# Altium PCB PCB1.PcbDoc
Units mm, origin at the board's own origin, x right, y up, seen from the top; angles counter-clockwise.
Board outline 70 x 70 mm, 4 copper layers (Top Layer, Internal Plane 1, Internal Plane 2, Bottom Layer), stack 0.462 mm thick; 10 components, 13 nets, 53 pads, 0 vias.
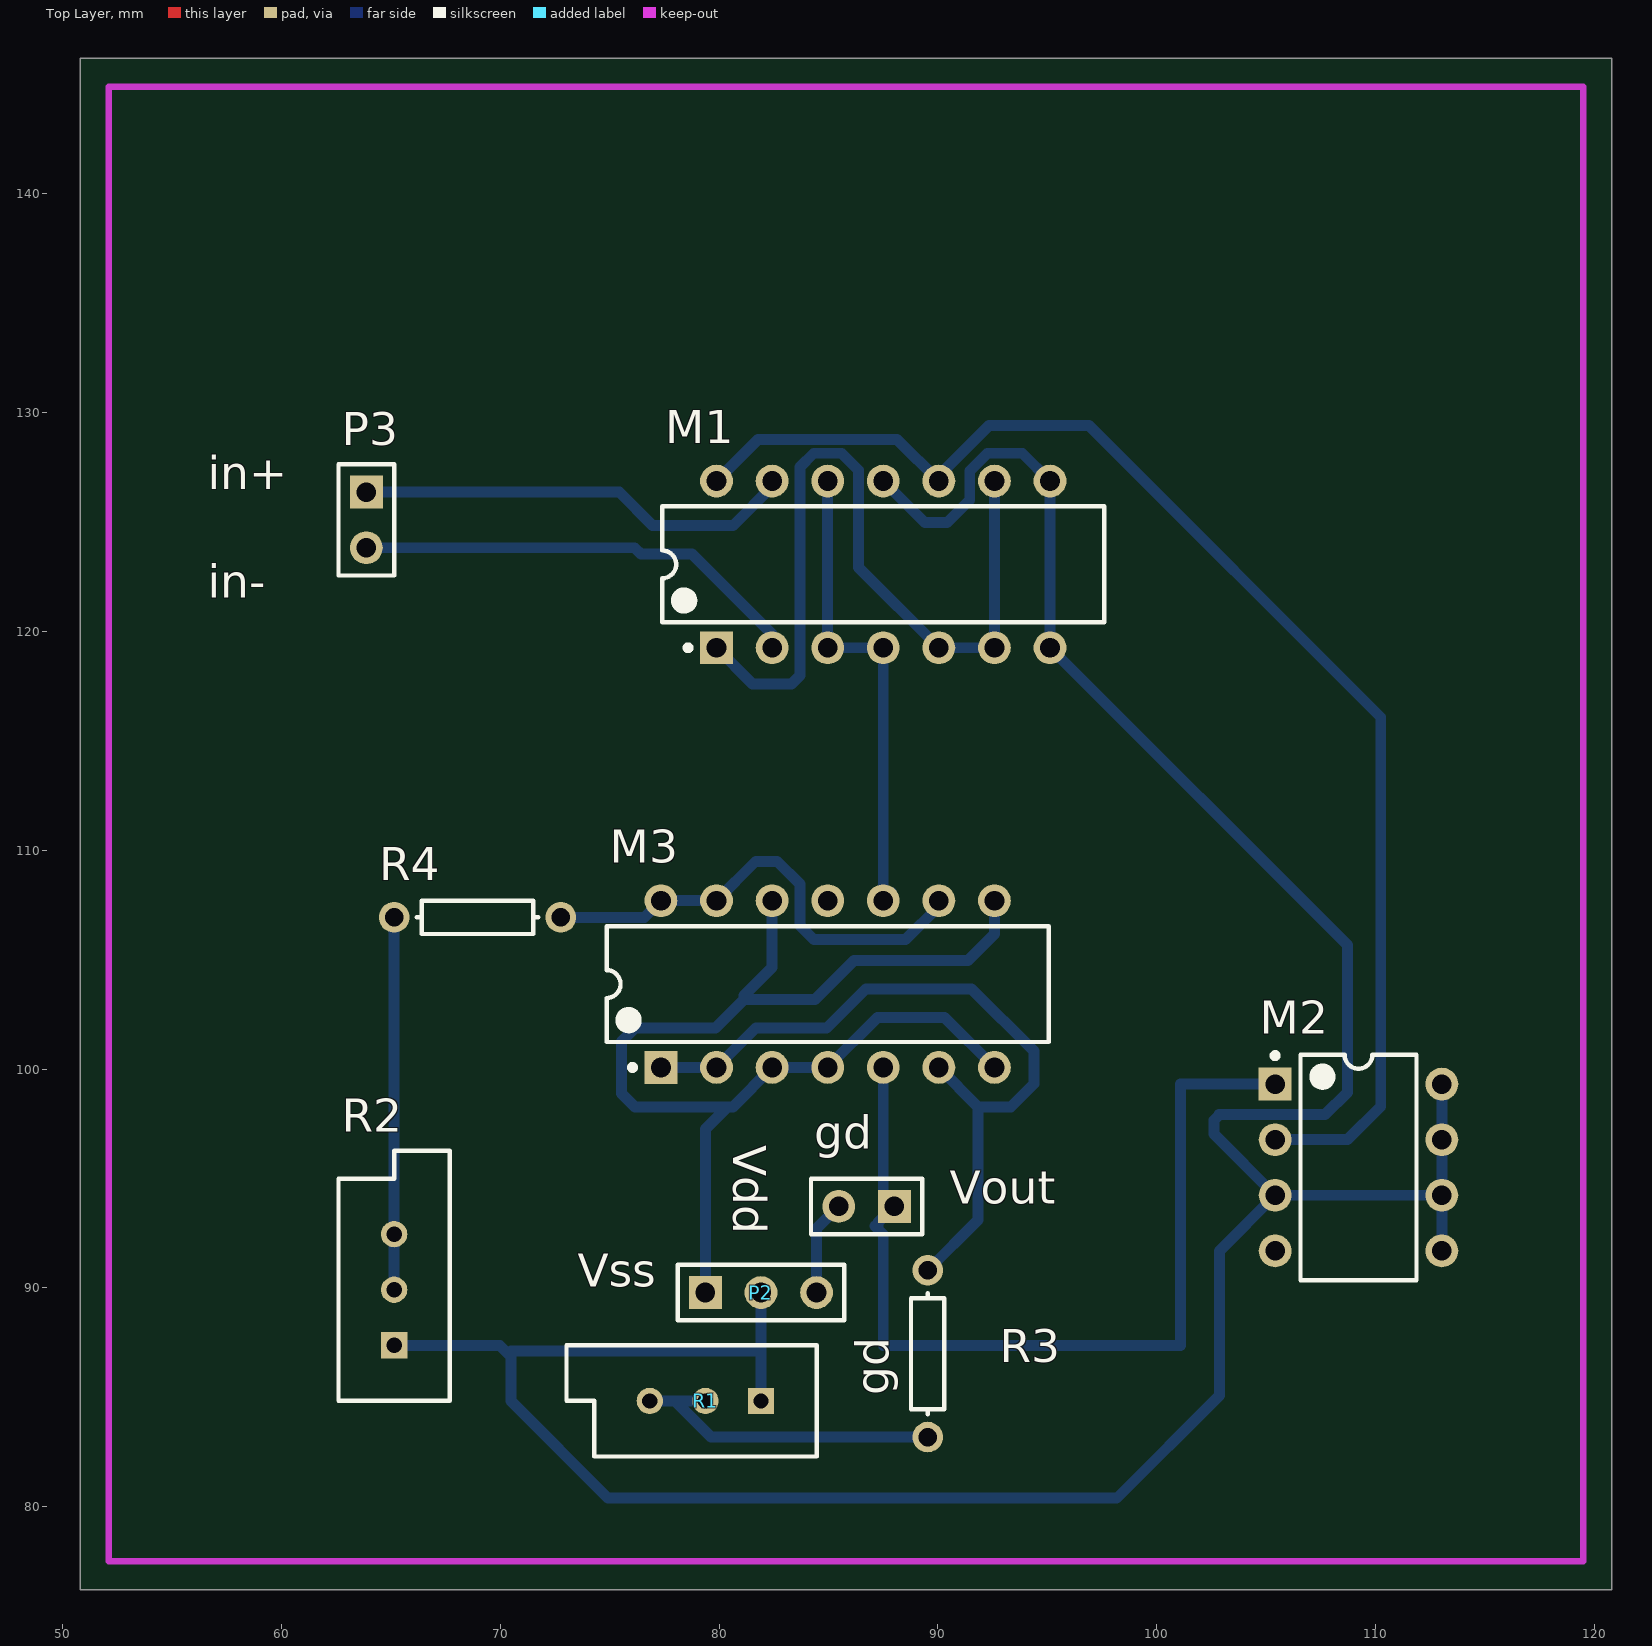
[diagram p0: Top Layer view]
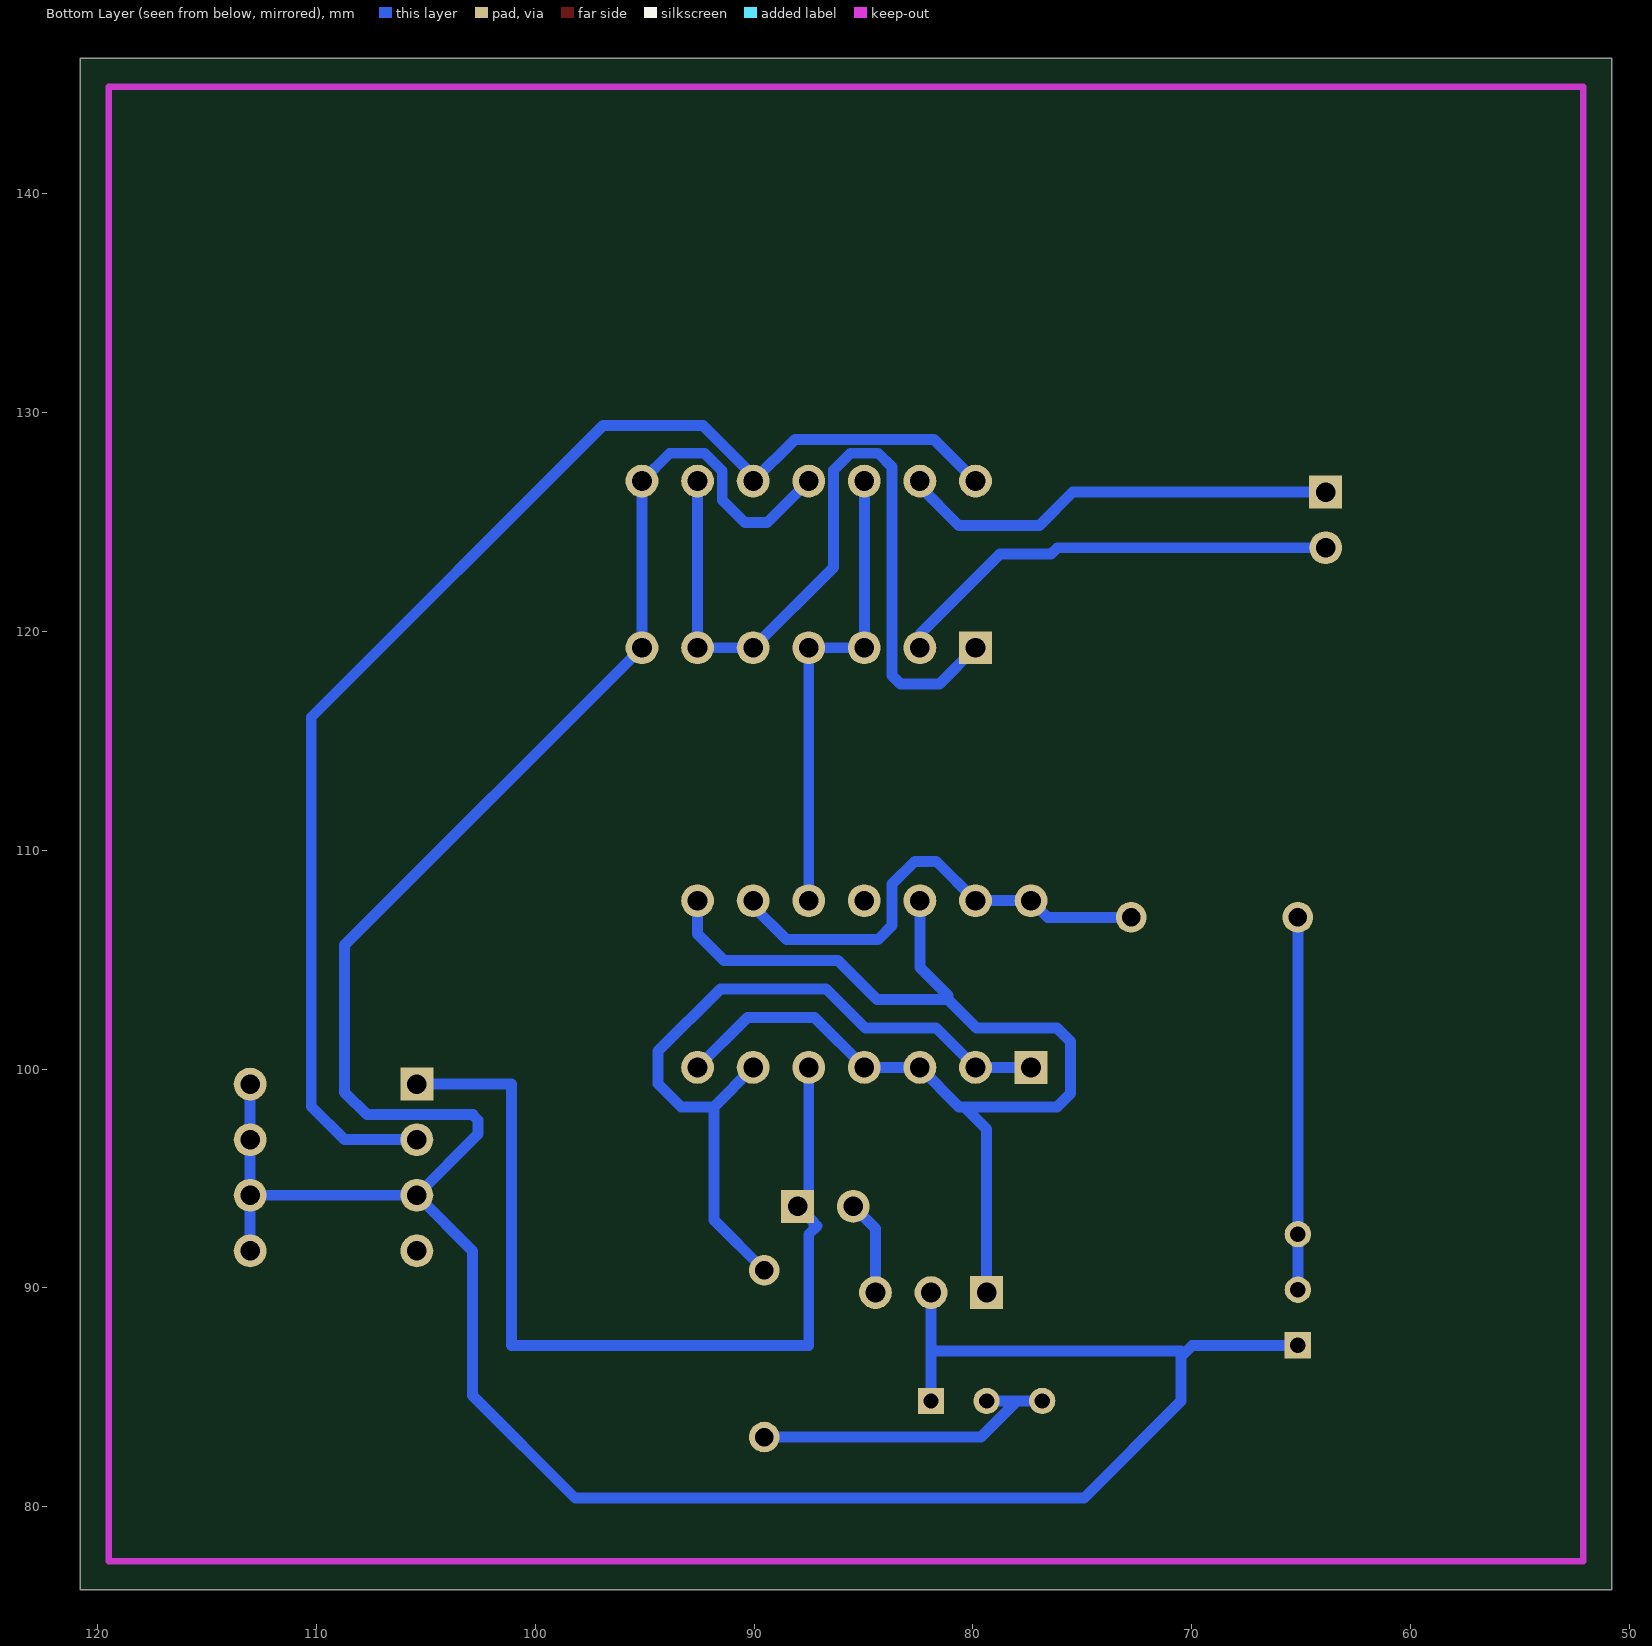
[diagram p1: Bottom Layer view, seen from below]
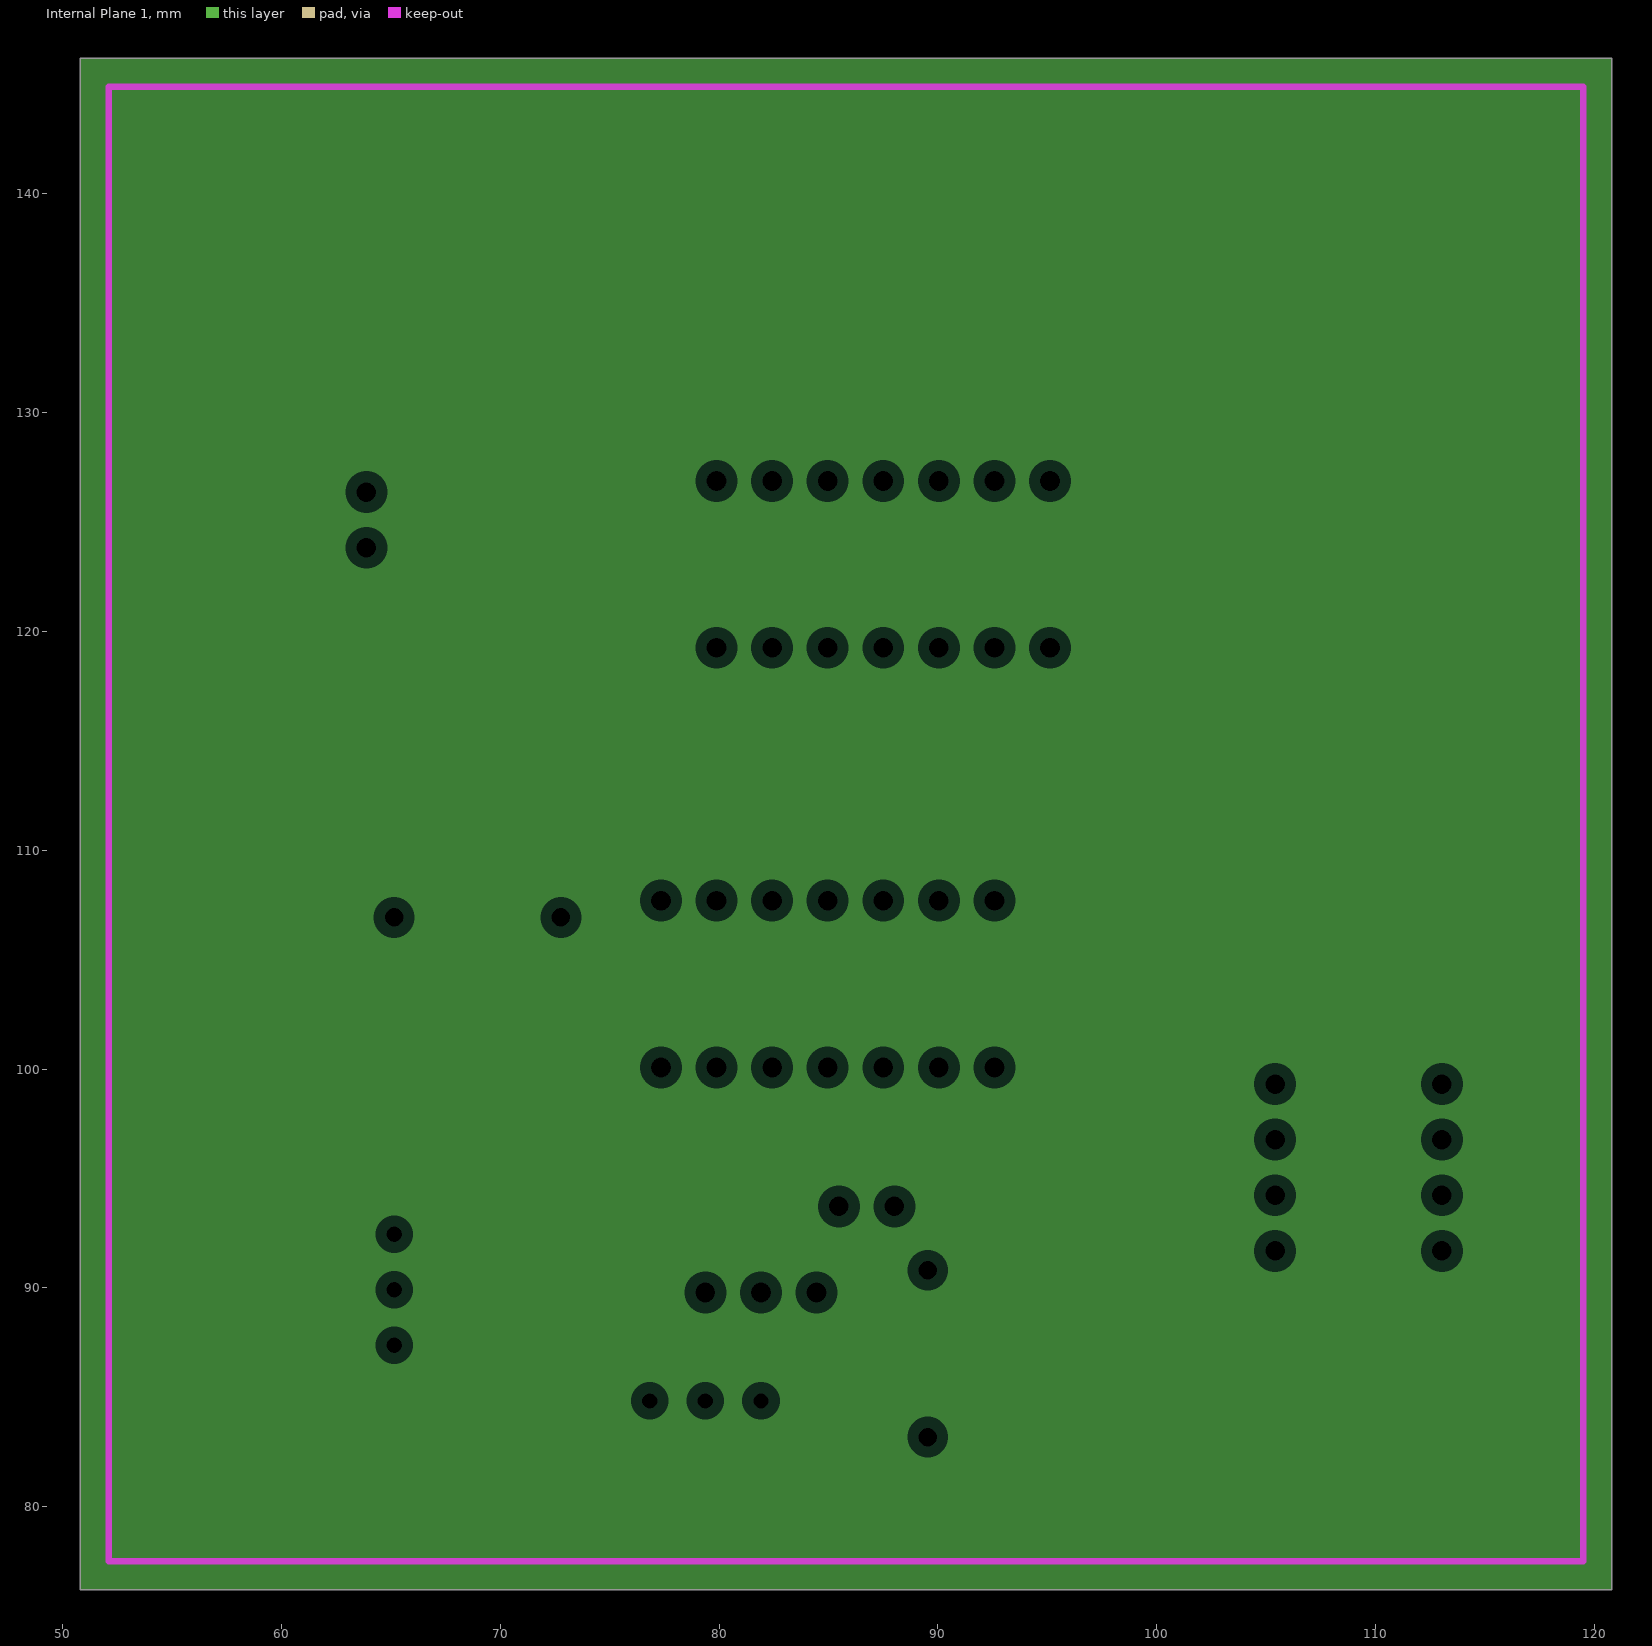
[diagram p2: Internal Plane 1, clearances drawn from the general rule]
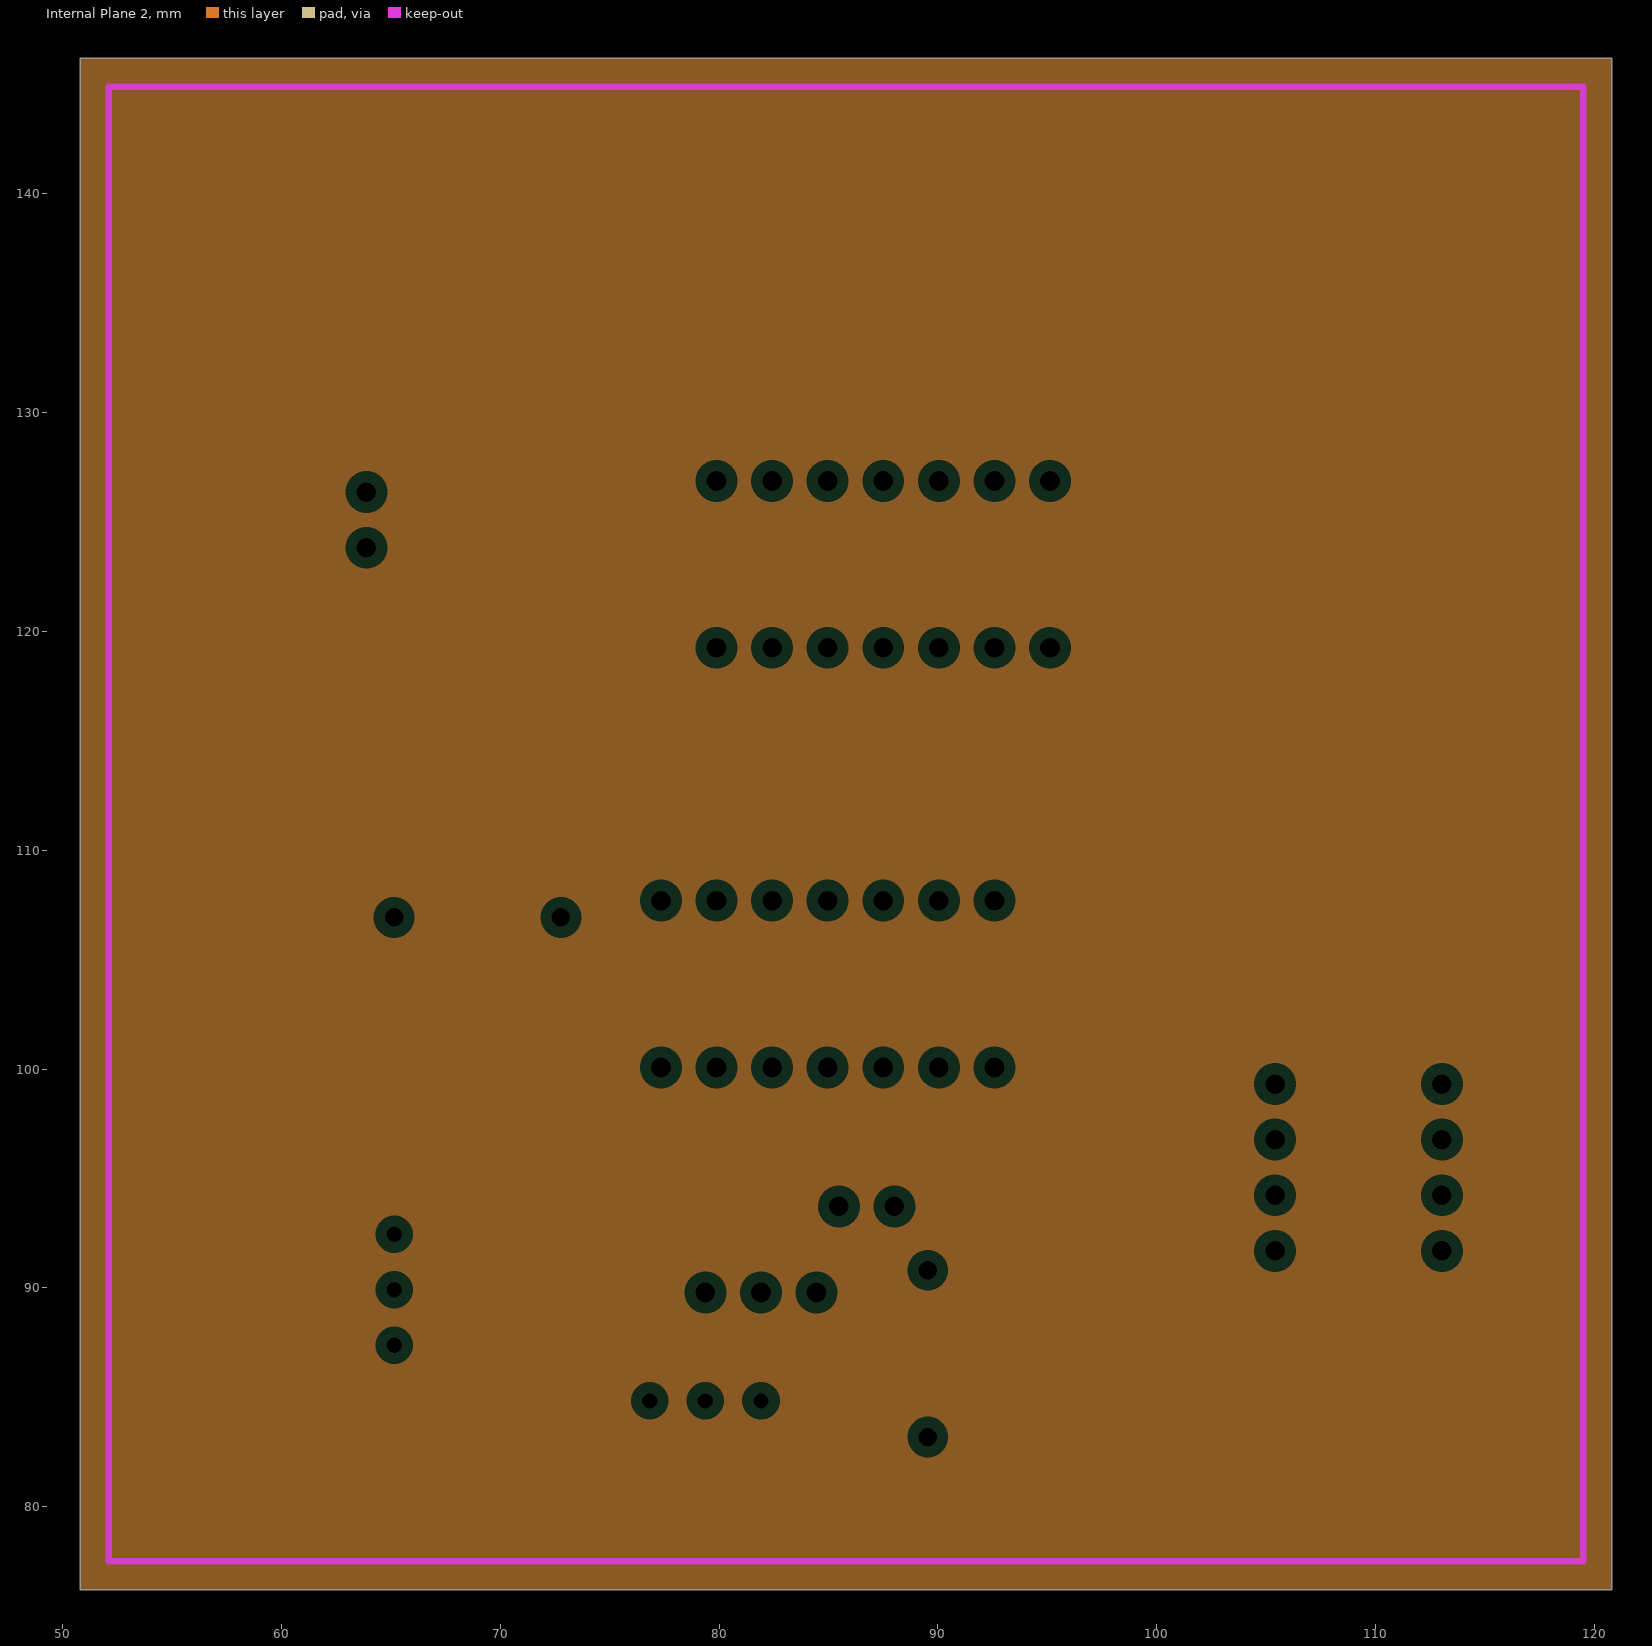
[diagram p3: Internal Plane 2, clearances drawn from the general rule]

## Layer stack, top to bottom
Top Solder: solder mask 0.0102, Solder Resist, Dk 3.5
Top Layer: signal copper 0.0356
Internal Plane 1: plane copper 0.0356
Internal Plane 2: plane copper 0.0356
Dielectric 1: dielectric 0.32, FR-4, Dk 4.8
Bottom Layer: signal copper 0.0356
Bottom Solder: solder mask 0.0102, Solder Resist, Dk 3.5

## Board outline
50.8,76.2 120.8,76.2 120.8,146.2 50.8,146.2

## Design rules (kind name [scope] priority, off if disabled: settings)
Clearance Clearance_3 [InNet('VDD')    or InNet('NetM3_9')] p1: gap=0.127
Clearance Clearance_2 [InNet('NetM1_1')] p2: gap=0.127
Clearance Clearance_1 [InNet('VDD')] p3: gap=0.127
Clearance [All] p4: gap=0.8
PlaneClearance [All] p1: clearance=0.508
PlaneConnect [All] p1: planeconnectstyle=Relief reliefexpansion=0.508 reliefentries=4 reliefconductorwidth=0.254 reliefairgap=0.254
PolygonConnect [All] p1: connectstyle=Relief reliefconductorwidth=0.254 reliefentries=4 polygonreliefangle="90 Angle" airgapwidth=0.254
RoutingVias [All] p1: holewidth=0.8 width=1.6 viastyle="Through Hole" minholewidth=0.711 minwidth=1.27 maxholewidth=0.711 maxwidth=1.27
SolderMaskExpansion [All] p1: expansion=0.102
Width [All] p1: maxlimit=0.5 minlimit=0.203 preferedwidth=0.5 toplayer_minwidth=0.5 minimp=50.000000 maximp=50.000000 favimp=50.000000
28 further rules are at their usual default settings.

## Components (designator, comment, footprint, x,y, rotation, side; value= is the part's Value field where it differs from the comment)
gd "Header 2" HDR1X2 88.011,93.726 r180 top (schematic designator P1)
M1 "ALD1105" DIP-14 87.503,123.063 r90 top
M2 "ALD1117" DIP-8 109.22,95.504 r0 top
M3 "ALD1106" DIP-14 84.963,103.886 r90 top
P2 "Header 3" HDR1X3 79.375,89.789 r0 top
P3 "Header 2" HDR1X2 63.881,126.365 r270 top
R1 "RPot" VR5 79.375,84.836 r180 top
R2 "RPot" VR5 65.151,89.916 r90 top
R3 "Res1" AXIAL-0.3 89.535,86.995 r90 top
R4 "Res1" AXIAL-0.3 68.961,106.934 r0 top

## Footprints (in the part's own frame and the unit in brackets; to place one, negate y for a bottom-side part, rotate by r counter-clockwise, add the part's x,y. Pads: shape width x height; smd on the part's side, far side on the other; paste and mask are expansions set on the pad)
AXIAL-0.3 [mm] "Axial Device, Thru-Hole; 2 Leads; 0.3 in Pin Spacing"
  round 1.4 hole 0.85: 1(-3.81,0) 2(3.81,0)
  silkscreen extent -2.77,-0.76 2.77,0.76
DIP-8 [mm] "DIP, 8-Pin, Row Spacing 7.62 mm, Pitch 2.54 mm"
  rect 1.5x1.5 hole 0.9: 1(-3.81,3.81)
  round 1.5 hole 0.9: 2(-3.81,1.27) 3(-3.81,-1.27) 4(-3.81,-3.81) 5(3.81,-3.81) 6(3.81,-1.27) 7(3.81,1.27) 8(3.81,3.81)
  silkscreen extent -3.93,-5.15 2.65,5.23, body extent -3.6,-5.15 3.6,5.15, height 5.33
DIP-14 [mm] "DIP, 14-Pin, Row Spacing 7.62 mm, Pitch 2.54 mm"
  rect 1.5x1.5 hole 0.9: 1(-3.81,7.62)
  round 1.5 hole 0.9: 2(-3.81,5.08) 3(-3.81,2.54) 4(-3.81,0) 5(-3.81,-2.54) 6(-3.81,-5.08) 7(-3.81,-7.62) 8(3.81,-7.62) 9(3.81,-5.08) 10(3.81,-2.54) 11(3.81,0) 12(3.81,2.54) 13(3.81,5.08) 14(3.81,7.62)
  silkscreen extent -3.93,-10.1 2.65,10.1, body extent -3.6,-10.1 3.6,10.1, height 5.08
HDR1X2 [mm] "Connector; Header; 2 Position"
  rect 1.5x1.5 hole 0.9: 1(0,0)
  round 1.5 hole 0.9: 2(2.54,0)
  silkscreen extent -1.27,-1.27 3.81,1.27
HDR1X3 [mm] "Connector; Header; 3 Position"
  rect 1.5x1.5 hole 0.9: 1(0,0)
  round 1.5 hole 0.9: 2(2.54,0) 3(5.08,0)
  silkscreen extent -1.27,-1.27 6.35,1.27
VR5 [mm] "Thru-Hole; 3 Leads"
  rect 1.2x1.2 hole 0.7: 1(-2.54,0)
  round 1.2 hole 0.7: 2(0,0) 3(2.54,0)
  silkscreen extent -5.08,-2.54 6.35,2.54

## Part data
gd P3: "Header, 2-Pin"
M1: "Dual P-channel and dual N-channel matched MOSFET array"
M2: "Dual P-channel matched MOSFET array"
M3: "Quad N-channel matched MOSFET array"
P2: "Header, 3-Pin"
R1 R2: "Potentiometer"
R3 R4: "Resistor"

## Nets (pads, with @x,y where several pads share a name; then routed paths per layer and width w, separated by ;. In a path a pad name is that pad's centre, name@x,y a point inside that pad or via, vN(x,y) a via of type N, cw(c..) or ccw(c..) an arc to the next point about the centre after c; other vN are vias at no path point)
GND: gd.2 P2.3 | length 4.4
  Bottom Layer w0.5: P2.3 84.455,92.71 gd.2
IN+: M1.13 P3.1 | length 19.9
  Bottom Layer w0.5: P3.1 75.438,126.365 76.962,124.841 80.645,124.841 M1.13@82.423,126.619
IN-: M1.2 P3.2 | length 20.2
  Bottom Layer w0.5: P3.2 76.14,123.825 76.424,123.541 78.77,123.541 M1.2@82.423,119.888
NetM1_1: M1.1 M1.5 M1.6 M1.9 | length 37.2
  Bottom Layer w0.5: M1.1 81.534,117.602 83.312,117.602 83.693,117.983 83.693,127.508 84.328,128.143 85.598,128.143 86.376,127.365 86.376,122.92 M1.5 M1.6 M1.9
NetM1_3: M1.3 M1.4 M1.12 M3.10 | length 22.3
  Bottom Layer w0.5: M1.12 M1.3 M1.4 M3.10 M3.10@87.884,108.077
NetM1_10: M1.10 M1.14 M2.2 | length 61.9
  Bottom Layer w0.5: M1.14 79.883,126.879 81.782,128.778 88.138,128.778 M1.10 90.043,127.127 92.329,129.413 96.901,129.413 110.236,116.078 110.236,98.298 108.712,96.774 M2.2
NetM3_1: M3.1 M3.2 M3.6 R3.2 | length 35.1
  Bottom Layer w0.5: M3.1 M3.2 79.883,100.082 81.677,101.876 84.919,101.876 86.705,103.662 91.543,103.662 94.383,100.822 94.383,99.33 93.329,98.276 91.837,98.276 ; R3.2 91.837,93.107 91.837,98.276 ; M3.6 90.043,100.07 91.837,98.276
NetM3_9: M3.9 M3.13 M3.14 R4.2 | length 21.6
  Bottom Layer w0.5: R4.2 76.581,106.934 M3.14 M3.13 79.883,107.702 81.677,109.496 82.655,109.496 83.693,108.458 83.693,106.553 84.328,105.918 88.519,105.918 M3.9@90.043,107.442
NetR1_2: R1.2 R1.3 R3.1 | length 14.8
  Bottom Layer w0.5: R1.3 77.978,84.836 ; R1.2 77.978,84.836 ; R3.1 79.629,83.185 77.978,84.836
NetR2_2: R2.2 R2.3 R4.1 | length 17
  Bottom Layer w0.5: R2.2 R2.3 R4.1
OUT2: gd.1 M2.1 M3.5 | length 43.4
  Bottom Layer w0.5: M3.5 87.503,94.234 gd.1 87.271,92.986 87.271,92.831 87.122,92.831 87.503,92.45 87.503,87.376 101.092,87.376 101.092,99.314 M2.1
VDD: M1.7 M1.8 M1.11 M2.3 M2.5 M2.6 M2.7 M2.8 P2.2 R1.1 R2.1 | length 141.6
  Bottom Layer w0.5: R2.1 69.977,87.376 70.485,86.868 ; R1.1 81.915,87.122 ; P2.2 81.915,87.122 ; M1.11 89.408,124.968 90.424,124.968 91.456,126 91.456,127.34 92.259,128.143 93.853,128.143 M1.8 M1.7 108.712,105.664 108.712,98.933 107.696,97.917 102.854,97.917 ; 102.854,97.901 102.616,97.663 102.616,97.028 M2.3 ; M2.5 M2.6 ; M2.8 M2.7 M2.6 ; 70.485,86.868 70.485,87.122 81.915,87.122 ; 70.485,86.868 70.485,84.836 74.93,80.391 98.171,80.391 102.87,85.09 102.87,91.694 M2.3 ; M2.3 M2.6
VSS: M3.3 M3.4 M3.7 M3.8 M3.12 P2.1 | length 56.7
  Bottom Layer w0.5: P2.1 79.375,97.26 80.391,98.276 ; 81.139,103.364 82.423,104.648 M3.12 ; M3.7 92.583,100.082 90.303,102.362 87.243,102.362 84.963,100.082 M3.4 M3.3 82.423,100.07 80.629,98.276 80.391,98.276 ; M3.8 92.583,106.172 91.373,104.962 86.166,104.962 84.38,103.176 81.139,103.176 79.839,101.876 76.158,101.876 75.543,101.261 75.543,98.891 76.158,98.276 80.391,98.276
pads on no net: M2.4 M3.11

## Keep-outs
Keep-Out Layer:
  lines w0.3: 52.1,77.5 52.1,144.9 119.5,144.9 119.5,77.5 52.1,77.5

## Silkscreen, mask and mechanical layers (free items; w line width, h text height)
Top Overlay:
  text "in+" at 56.642,126.492 h1.52
  text "in-" at 56.642,121.539 h1.52
  text "Vdd" at 80.645,96.52 h1.52 r270
  text "Vout" at 90.551,93.853 h1.52
  text "Vss" at 73.533,90.043 h1.52
  text "gd" at 87.757,85.09 h1.52 r90
Drill Drawing:
  text ".LEGEND" at 125.88,81.28 h1.52
  text "Drill Drawing." at 125.88,78.74 h1.52

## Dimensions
52.1,77.5 to 52.1,144.9 on Mechanical 1
52.1,77.5 to 119.5,77.5 on Mechanical 1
